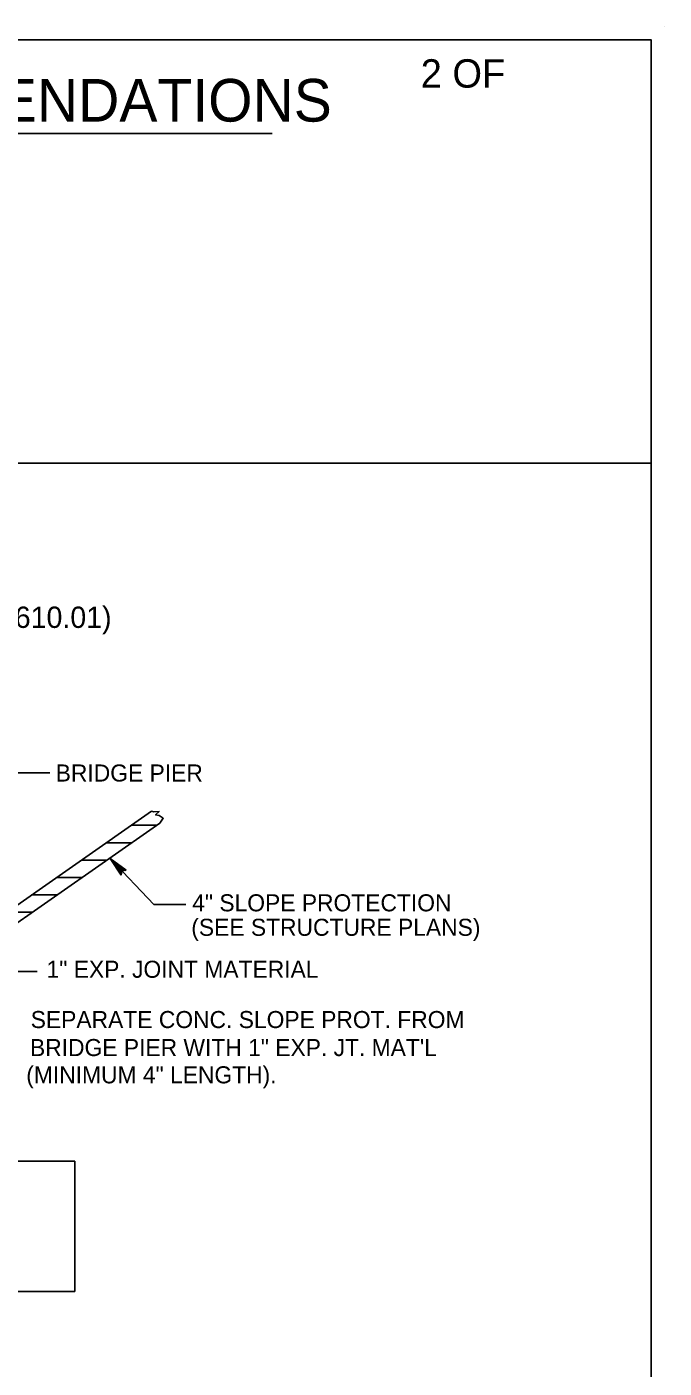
# Model space of a CAD drawing. Extents: x 1553195 to 1553792, y 810516 to 810787.
# Drawn here: x 1553772.77 to 1553792.37, y 810723.14 to 810764.42 of the extents above; entities that cross this region are included whole.
import ezdxf

# ---------------------------------------------------------------- set-up
doc = ezdxf.new("R2010")
doc.units = 0
doc.layers.add('Old_Level_28', color=7, linetype='Continuous')

msp = doc.modelspace()

# ---------------------------------------------------------------- linework, layer by layer
at = {"layer": 'Old_Level_28'}
for p, q in [((1553792.373, 810764.417), (1553792.373, 810764.417)), ((1553752.363, 810761.134), (1553780.316, 810761.134)), ((1553739.439, 810750.993), (1553791.973, 810750.993)), ((1553773.479, 810741.457), (1553772.494, 810741.457)), ((1553771.344, 810736.595), (1553776.608, 810740.281)), ((1553771.324, 810736.035), (1553776.864, 810739.914)), ((1553776.003, 810739.846), (1553776.764, 810739.846)), ((1553776.843, 810740.151), (1553776.843, 810740.151)), ((1553776.881, 810739.939), (1553776.864, 810739.914)), ((1553775.214, 810739.311), (1553776.003, 810739.311)), ((1553774.455, 810738.774), (1553775.243, 810738.774)), ((1553776.679, 810737.408), (1553775.337, 810738.822)), ((1553775.337, 810738.822), (1553775.826, 810738.461)), ((1553775.337, 810738.822), (1553775.67, 810738.315)), ((1553775.675, 810738.334), (1553775.337, 810738.822)), ((1553775.337, 810738.822), (1553775.677, 810738.353)), ((1553775.682, 810738.37), (1553775.337, 810738.822)), ((1553775.337, 810738.822), (1553775.683, 810738.39)), ((1553775.688, 810738.408), (1553775.337, 810738.822)), ((1553775.337, 810738.822), (1553775.69, 810738.428)), ((1553775.695, 810738.445), (1553775.337, 810738.822)), ((1553775.715, 810738.445), (1553775.337, 810738.822)), ((1553775.337, 810738.822), (1553775.731, 810738.451)), ((1553775.748, 810738.451), (1553775.337, 810738.822)), ((1553775.337, 810738.822), (1553775.768, 810738.457)), ((1553775.786, 810738.457), (1553775.337, 810738.822)), ((1553775.337, 810738.822), (1553775.808, 810738.459)), ((1553773.695, 810738.242), (1553774.477, 810738.242)), ((1553775.67, 810738.315), (1553775.695, 810738.445)), ((1553775.695, 810738.445), (1553775.826, 810738.461)), ((1553772.914, 810737.704), (1553773.717, 810737.704)), ((1553777.664, 810737.408), (1553776.679, 810737.408)), ((1553772.159, 810737.168), (1553772.948, 810737.168)), ((1553773.09, 810735.35), (1553772.106, 810735.35)), ((1553771.348, 810729.513), (1553774.248, 810729.513)), ((1553774.248, 810729.513), (1553774.248, 810725.497)), ((1553774.248, 810725.497), (1553764.422, 810725.497))]:
    msp.add_line(p, q, dxfattribs=at)
msp.add_lwpolyline([(1553739.439, 810764.018), (1553791.973, 810764.018), (1553791.973, 810694.817), (1553739.439, 810694.817)], close=True, dxfattribs=at)
msp.add_lwpolyline([(1553776.881, 810739.939), (1553776.968, 810740.064), (1553776.843, 810740.151), (1553776.732, 810740.164), (1553776.843, 810740.272), (1553776.683, 810740.262), (1553776.608, 810740.281)], dxfattribs=at)

# ---------------------------------------------------------------- texts
for s, height, p in [('2 OF   ', 0.8749, (1553784.886, 810762.545)), ('STRUCTURE RECOMMENDATIONS', 1.31234, (1553752.611, 810761.501)), ('(USE IN CONJUNCTION WITH STD NO. 610.01)', 0.65617, (1553756.025, 810745.92)), ('BRIDGE PIER', 0.52493, (1553773.661, 810741.193)), ('4" SLOPE PROTECTION', 0.52493, (1553777.86, 810737.198)), ('(SEE STRUCTURE PLANS)', 0.52493, (1553777.831, 810736.445)), ('1" EXP. JOINT MATERIAL', 0.52493, (1553773.381, 810735.153)), ('SEPARATE CONC. SLOPE PROT. FROM', 0.52493, (1553772.893, 810733.606)), ('BRIDGE PIER WITH 1" EXP. JT. MAT\'L', 0.52493, (1553772.871, 810732.744)), ('(MINIMUM 4" LENGTH).', 0.52493, (1553772.756, 810731.905))]:
    msp.add_text(s, height=height, dxfattribs=at).set_placement(p)

doc.saveas('drawing.dxf')
